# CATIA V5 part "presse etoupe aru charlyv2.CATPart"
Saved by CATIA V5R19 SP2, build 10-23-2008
Part number: Part38
Bounding box of the stored display mesh (mm): x -22.5 to 22.5, y -17.2 to 7, z -16 to 16
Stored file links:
  Z:\presse etoupe aru charlyv2.CATPart
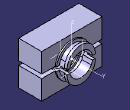
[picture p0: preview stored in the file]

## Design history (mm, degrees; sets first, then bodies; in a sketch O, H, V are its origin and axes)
AxisSystem1: origin (0, 0, 0), X (1, 0, 0), Y (0, 1, 0), Z (0, 0, 1)
Body1 (main body)
  Sketch1 on XY plane of AxisSystem1, origin (0, 0, 0), H (1, 0, 0), V (0, 1, 0)
    axis line L1 (0, 46.7237) -> (0, -31.7)
    point P1 (0, 46.7237)
    point P3 (8.5, 0)
    line L2 (8.5, 0) -> (8.5, 7)
    line L3 (8.5, 7) -> (12.5, 7)
    line L4 (12.5, 7) -> (12.5, 5)
    line L5 (12.5, 5) -> (10.5, 5)
    line L6 (10.5, 5) -> (10.5, 1)
    line L7 (10.5, 1) -> (12.5, 1)
    point P9 (12.5, 1)
    line L8 (12.5, 1) -> (12.5, 0)
    line L9 (12.5, 0) -> (15.5, 0)
    line L10 (15.5, 0) -> (15.5, -17.2)
    line L11 (15.5, -17.2) -> (11, -17.2)
    line L12 (11, -17.2) -> (11, -16.2)
    line L13 (11, -16.2) -> (12.5, -16.2)
    line L14 (12.5, -16.2) -> (12.5, -13.4)
    line L15 (12.5, -13.4) -> (11, -13.4)
    point P17 (11, -13.4)
    line L16 (11, -13.4) -> (11, -12.4)
    line L17 (11, -12.4) -> (12.5, -12.4)
    point P19 (12.5, -12.4)
    line L18 (12.5, -12.4) -> (12.5, -9.6)
    line L19 (12.5, -9.6) -> (11, -9.6)
    point P21 (11, -9.6)
    line L20 (11, -9.6) -> (11, -8.6)
    line L21 (11, -8.6) -> (12.5, -8.6)
    point P23 (12.5, -8.6)
    line L22 (12.5, -8.6) -> (12.5, -5.8)
    line L23 (12.5, -5.8) -> (11, -5.8)
    point P25 (11, -5.8)
    line L24 (11, -5.8) -> (11, -4.8)
    line L25 (11, -4.8) -> (12.5, -4.8)
    point P27 (12.5, -4.8)
    line L26 (12.5, -4.8) -> (12.5, -2)
    point P28 (12.5, -2)
    line L27 (12.5, -2) -> (8.5, 0)
    reference intersected line E1 through (0, 0) direction (0, 1) from YZ plane of AxisSystem1
    reference projected line E2 through (0, 0) direction (1, 0) from edge [XY plane of AxisSystem1 | ZX plane of AxisSystem1]
    "Radius" L4 L1 = 12.5
    distance L14 L10 = 3
    "Radius" L14 L1 = 12.5
    distance L11 L13 = 1
    distance L13 L15 = 2.8
    distance L15 L17 = 1 {= Sketch1.distance(L11 L13)}
    distance L17 L19 = 2.8 {= Sketch1.distance(L13 L15)}
    distance L19 L21 = 1 {= Sketch1.distance(L11 L13)}
    distance L12 L14 = 1.5
    distance L21 L23 = 2.8 {= Sketch1.distance(L13 L15)}
    distance L23 L25 = 1 {= Sketch1.distance(L11 L13)}
    length L26 = 2.8 {= Sketch1.distance(L13 L15)}
    distance L7 L9 = 1
    length L4 = 2
    distance L5 L7 = 4
    "Radius" L6 L1 = 10.5
    distance L2 L6 = 2
    "Radius" L2 L1 = 8.5 (reference)
    distance P28 L9 = 2
    coincidence: P1 V, P9 L4, P17 L12, P19 L14, P21 L12, P23 L14, P25 L12, P27 L14, L1 E1, L9 E2, P3 L9
    vertical: L1 V, L2 V, L4 V, L6 V, L8 V, L10 V, L12 V, L14 V, L16 V, L18 V, L20 V, L22 V, L24 V, L26 V
    horizontal: L3 H, L5 H, L7 H, L9 H, L11 H, L13 H, L15 H, L17 H, L19 H, L21 H, L23 H, L25 H
  Shaft1: profile Sketch1, axis Sketch1.L1, angle 360
  Sketch2 on ZX plane of AxisSystem1, origin (0, 0, 0), H (0, 0, 1), V (1, 0, 0)
    line L1 (-16, 22.5) -> (16, 22.5)
    line L2 (16, 22.5) -> (16, -22.5)
    line L3 (16, -22.5) -> (-16, -22.5)
    line L4 (-16, -22.5) -> (-16, 22.5)
    reference projected line E1 through (0, 0) direction (0, 1) from edge [XY plane of AxisSystem1 | ZX plane of AxisSystem1]
    reference projected line E2 through (0, 0) direction (1, 0) from edge [ZX plane of AxisSystem1 | YZ plane of AxisSystem1]
    projected circle E3 centre (0, 0) radius 15.5 from edge [face of Shaft1 from Sketch1.L9 | face of Shaft1 from Sketch1.L10]
    distance L4 L2 = 32
    distance L1 L3 = 45
    horizontal: L1 H, L3 H
    vertical: L2 V, L4 V
    symmetry: L2 L4 E1, L3 L1 E2
  Pad1: profile Sketch2, direction (0, -1, 0), up to face of Shaft1 from Sketch1.L11
  Sketch3 on XY plane of AxisSystem1, origin (0, 0, 0), H (1, 0, 0), V (0, 1, 0)
    point P1 (18.5, -8.6)
    line L1 (24.5, 0) -> (24.5, -17.2)
    line L2 (24.5, -17.2) -> (12.5, -17.2)
    line L3 (12.5, -17.2) -> (12.5, 0)
    line L4 (12.5, 0) -> (24.5, 0)
    reference projected line E1 through (0, 0) direction (0, -1) from axis of face of Shaft1 from Sketch1.L10
    reference intersected line E2 through (0, 0) direction (1, 0) from face of Shaft1 from Sketch1.L9
    reference intersected line E3 through (0, -17.2) direction (1, 0) from face of Shaft1 from Sketch1.L11
    distance L3 E1 = 12.5
    distance L1 L3 = 12
    vertical: L1 V, L3 V
    horizontal: L2 H, L4 H
    equidistance: L1 L3 P1, L2 L4 P1
    coincidence: L4 E2, L2 E3
  Pad2: profile Sketch3, direction (0, 0, 1), length 4, mirrored extent, deactivated
  Sketch4 on end face of Pad2, origin (18.9633, -7.2019, 4), H (1, 0, 0), V (0, 1, 0)
    point P1 (1.5367, -1.9981)
    reference intersected line E1 (5.5367, 7.2019) -> (5.5367, -9.9981) from face of Pad2 from Sketch3.L1
    reference intersected line E2 through (0, -9.9981) direction (1, 0) from face of Pad2
    distance P1 E1 = 4
    distance P1 E2 = 8
  Hole1: placed by Sketch4, at (20.5, -9.2, 4) direction (0, 0, -1), diameter 3.5, through (limit type 3), deactivated
  Mirror1: of Pad2, Hole1, about YZ plane of AxisSystem1, deactivated
  Fillet1: radius 5, on edge [face of Mirror1 | face of Mirror1] (x2); edge [face of Mirror1 | face of Pad2 from Sketch3.L1]; edge [face of Pad2 from Sketch3.L1 | face of Mirror1], deactivated
  Fillet2: radius 2, on edge [face of Shaft1 from Sketch1.L10 | end face of Pad2]; edge [start face of Pad2 | face of Shaft1 from Sketch1.L10]; edge [face of Mirror1 | face of Shaft1 from Sketch1.L10]; edge [face of Shaft1 from Sketch1.L10 | face of Mirror1], deactivated
  Sketch5 on YZ plane of AxisSystem1, origin (0, 0, 0), H (0, 1, 0), V (0, 0, 1)
    point P1 (-5.1, 0)
    line L1 (7, 1.5) -> (7, -1.5)
    line L2 (7, -1.5) -> (-17.2, -1.5)
    line L3 (-17.2, -1.5) -> (-17.2, 1.5)
    line L4 (-17.2, 1.5) -> (7, 1.5)
    reference intersected line E1 through (7, 0) direction (0, -1) from face of Shaft1 from Sketch1.L3
    reference intersected line E2 through (-17.2, 0) direction (0, -1) from face of Mirror1
    length L1 = 3
    coincidence: P1 H, L1 E1, L3 E2
    vertical: L1 V, L3 V
    horizontal: L2 H, L4 H
    equidistance: L1 L3 P1, L2 L4 P1
  Pocket1: profile Sketch5, direction (-1, 0, 0), through (limit type 6), opposite side through (limit type 6)
  Sketch6 on face of Shaft1 from Sketch1.L3, origin (8.5, 7, 0), H (1, 0, 0), V (0, 0, 1)
    construction line L1 (-8.5, 2) -> (-8.5, -2)
    point P1 (-8.5, 2)
    point P2 (-8.5, -2)
    line L2 (2, 2) -> (2, -2)
    line L3 (-19, -2) -> (-19, 2)
    arc A1 centre (-8.5, -2) radius 10.5 from (2, -2) to (-19, -2) cw
    arc A2 centre (-8.5, 2) radius 10.5 from (-19, 2) to (2, 2) cw
    reference projected line E1 through (0, 0) direction (1, 0) from edge [XY plane of AxisSystem1 | ZX plane of AxisSystem1]
    reference projected line E2 through (-8.5, 0) direction (0, 1) from edge [ZX plane of AxisSystem1 | YZ plane of AxisSystem1]
    distance L1 L2 = 10.5
    length L1 = 4
    vertical: L1 V
    tangency: A1 L2, A2 L2, A1 L3, A2 L3
    symmetry: P1 P2 E1
    coincidence: L1 E2
  Pocket2: profile Sketch6, direction (0, -1, 0), length 3, outer side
